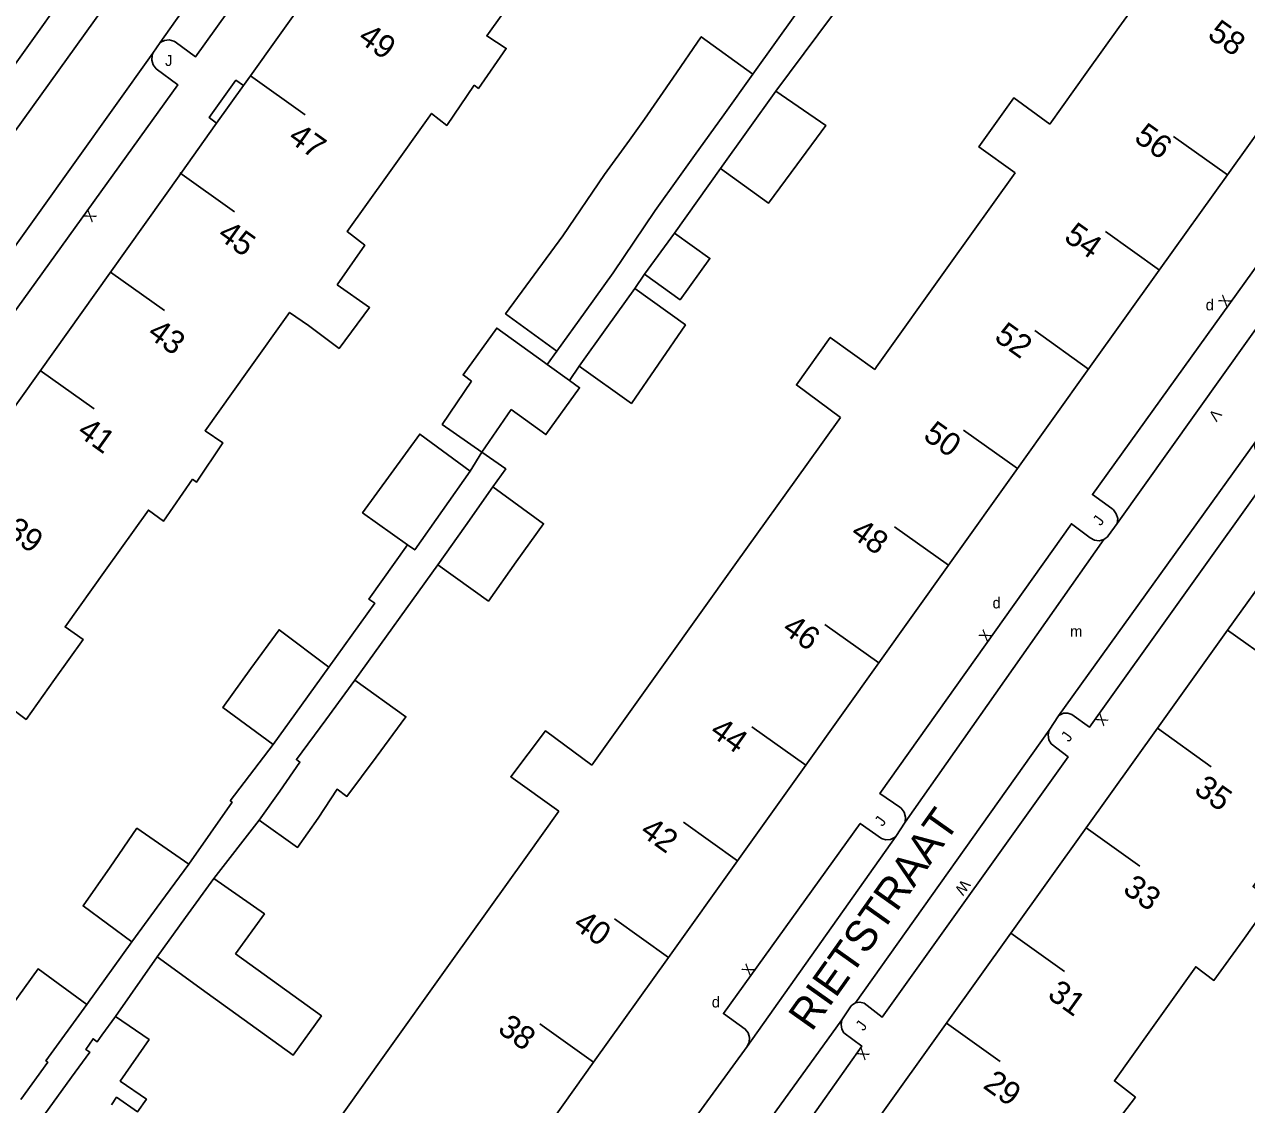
# Model space of a CAD drawing. Extents: x 134999 to 136502, y 457398 to 459002.
# Drawn here: x 135503.6 to 135559.1, y 457437.9 to 457486.9 of the extents above; entities that cross this region are included whole.
import ezdxf

# ---------------------------------------------------------------- set-up
doc = ezdxf.new("R2010")
doc.units = 0
for name, color, linetype in [('RI_DGTB_15', 7, 'Continuous'), ('RI_DGTB_29', 7, 'Continuous'), ('RI_DGTB_30', 7, 'Continuous'), ('RI_DGTB_31', 7, 'Continuous'), ('RI_DGTB_36', 7, 'Continuous'), ('RI_DGTB_37', 7, 'Continuous'), ('RI_DGTB_4', 7, 'Continuous'), ('RI_DGTB_43', 7, 'Continuous'), ('RI_DGTB_5', 7, 'Continuous'), ('RI_DGTB_53', 7, 'Continuous'), ('RI_DGTB_54', 7, 'Continuous'), ('RI_DGTB_6', 7, 'Continuous')]:
    doc.layers.add(name, color=color, linetype=linetype)

msp = doc.modelspace()

# ---------------------------------------------------------------- linework, layer by layer
at = {"layer": 'RI_DGTB_15'}
for p, q in [((135513.871, 457484.606), (135516.353, 457482.837)), ((135558.196, 457480.112), (135555.756, 457481.857)), ((135510.663, 457480.201), (135513.152, 457478.428)), ((135555.111, 457475.794), (135552.671, 457477.539)), ((135507.523, 457475.702), (135509.967, 457473.961)), ((135551.902, 457471.303), (135549.462, 457473.048)), ((135504.338, 457471.235), (135506.782, 457469.494)), ((135548.672, 457466.786), (135546.232, 457468.531)), ((135545.54, 457462.402), (135543.1, 457464.147)), ((135542.378, 457457.978), (135539.938, 457459.723)), ((135558.204, 457459.461), (135560.644, 457457.716)), ((135539.066, 457453.339), (135536.626, 457455.084)), ((135555.022, 457455.013), (135557.462, 457453.268)), ((135535.965, 457449.003), (135533.525, 457450.748)), ((135551.792, 457450.499), (135554.232, 457448.754)), ((135532.834, 457444.622), (135530.394, 457446.367)), ((135548.374, 457445.722), (135550.814, 457443.977)), ((135529.439, 457439.866), (135526.999, 457441.611)), ((135545.453, 457441.638), (135547.893, 457439.893))]:
    msp.add_line(p, q, dxfattribs=at)
at = {"layer": 'RI_DGTB_4'}
for p, q in [((135513.871, 457484.606), (135517.081, 457489.108)), ((135558.196, 457480.112), (135561.66, 457484.96)), ((135513.871, 457484.606), (135513.552, 457484.159)), ((135512.332, 457482.447), (135513.552, 457484.159)), ((135510.708, 457480.169), (135512.332, 457482.447)), ((135507.488, 457475.653), (135510.708, 457480.169)), ((135558.196, 457480.112), (135555.11, 457475.795)), ((135504.31, 457471.196), (135507.488, 457475.653)), ((135555.11, 457475.795), (135551.918, 457471.328)), ((135501.103, 457466.696), (135504.31, 457471.196)), ((135551.918, 457471.328), (135548.672, 457466.786)), ((135548.672, 457466.786), (135545.54, 457462.402)), ((135561.424, 457463.961), (135558.204, 457459.461)), ((135545.54, 457462.402), (135542.378, 457457.978)), ((135558.204, 457459.461), (135555.022, 457455.013)), ((135542.378, 457457.978), (135539.064, 457453.34)), ((135555.022, 457455.013), (135551.792, 457450.499)), ((135539.064, 457453.34), (135535.965, 457449.003)), ((135551.792, 457450.499), (135548.374, 457445.722)), ((135535.965, 457449.003), (135532.834, 457444.622)), ((135548.374, 457445.722), (135545.483, 457441.681)), ((135532.834, 457444.622), (135529.437, 457439.868)), ((135545.483, 457441.681), (135542.188, 457437.075)), ((135529.437, 457439.868), (135526.186, 457435.319))]:
    msp.add_line(p, q, dxfattribs=at)
at = {"layer": 'RI_DGTB_5'}
for p, q in [((135553.28, 457486.793), (135555.007, 457489.21)), ((135551.826, 457484.76), (135553.28, 457486.793)), ((135550.149, 457482.415), (135551.826, 457484.76)), ((135545.562, 457475.998), (135548.571, 457480.206)), ((135542.276, 457471.401), (135545.562, 457475.998)), ((135542.197, 457471.29), (135542.276, 457471.401)), ((135539.115, 457466.979), (135540.639, 457469.11)), ((135535.932, 457462.526), (135539.115, 457466.979)), ((135532.617, 457457.889), (135535.932, 457462.526)), ((135529.436, 457453.44), (135532.617, 457457.889)), ((135529.364, 457453.34), (135529.436, 457453.44)), ((135526.365, 457449.147), (135527.868, 457451.249)), ((135523.015, 457444.461), (135526.365, 457449.147)), ((135519.734, 457439.872), (135523.015, 457444.461)), ((135516.628, 457435.527), (135519.734, 457439.872)), ((135552.594, 457436.415), (135554.027, 457438.286))]:
    msp.add_line(p, q, dxfattribs=at)
for points in [[(135526.629, 457489.259), (135524.594, 457486.409), (135525.48, 457485.848), (135524.219, 457484.027), (135524.025, 457484.179)], [(135520.093, 457480.103), (135522.087, 457482.896), (135522.781, 457482.351), (135524.025, 457484.179)], [(135550.149, 457482.415), (135548.511, 457483.611), (135546.921, 457481.381), (135548.571, 457480.206)], [(135520.093, 457480.103), (135518.263, 457477.539), (135519.057, 457476.921), (135517.804, 457475.13)], [(135517.804, 457475.13), (135519.279, 457474.088), (135517.89, 457472.24), (135516.505, 457473.273)], [(135513.724, 457471.182), (135515.646, 457473.874), (135516.505, 457473.273)], [(135542.197, 457471.29), (135540.182, 457472.738), (135538.645, 457470.584), (135540.639, 457469.11)], [(135513.724, 457471.182), (135511.815, 457468.507), (135512.624, 457467.952), (135511.426, 457466.177), (135511.247, 457466.315)], [(135507.296, 457462.175), (135509.244, 457464.904), (135509.931, 457464.411), (135511.247, 457466.315)], [(135507.296, 457462.175), (135505.462, 457459.607), (135506.281, 457459.044), (135504.985, 457457.229)], [(135501.011, 457453.375), (135502.898, 457456.015), (135503.689, 457455.414), (135504.985, 457457.229)], [(135527.868, 457451.249), (135525.683, 457452.814), (135527.252, 457454.893), (135529.364, 457453.34)], [(135561.294, 457450.532), (135559.367, 457447.834), (135560.203, 457447.21), (135558.896, 457445.392)], [(135554.653, 457441.236), (135556.766, 457444.193), (135557.589, 457443.574), (135558.896, 457445.392)], [(135554.027, 457438.286), (135553.07, 457439.02), (135554.653, 457441.236)]]:
    msp.add_lwpolyline(points, dxfattribs=at)
at = {"layer": 'RI_DGTB_53'}
for p, q in [((135517.563, 457497.101), (135509.776, 457486.117)), ((135500, 457477.662), (135510.887, 457492.825)), ((135509.439, 457485.634), (135500, 457472.409)), ((135562.247, 457477), (135553.203, 457464.297)), ((135559.48, 457467.998), (135550.538, 457455.574)), ((135552.587, 457463.573), (135543.575, 457450.749)), ((135541.331, 457442.565), (135550.114, 457454.92)), ((135543.156, 457450.102), (135536.405, 457440.579)), ((135537.288, 457437.052), (135540.711, 457441.792))]:
    msp.add_line(p, q, dxfattribs=at)
at = {"layer": 'RI_DGTB_54'}
for p, q in [((135541.104, 457488.454), (135537.703, 457483.901)), ((135536.671, 457484.682), (135538.65, 457487.441)), ((135509.776, 457486.117), (135509.439, 457485.634)), ((135535.2, 457480.403), (135533.116, 457477.472)), ((135531.306, 457474.955), (135531.754, 457475.606)), ((135523.845, 457466.679), (135524.377, 457467.527)), ((135522.369, 457462.423), (135518.611, 457457.191)), ((135550.538, 457455.574), (135550.114, 457454.92)), ((135514.91, 457454.273), (135512.947, 457451.728)), ((135514.264, 457450.838), (135512.206, 457448.191)), ((135543.575, 457450.749), (135543.156, 457450.102)), ((135508.49, 457445.331), (135506.448, 457442.484)), ((135536.405, 457440.579), (135527.712, 457428.631))]:
    msp.add_line(p, q, dxfattribs=at)
for points in [[(135517.563, 457497.101), (135517.532, 457496.969), (135517.545, 457496.744), (135517.635, 457496.538), (135517.791, 457496.376), (135518.719, 457495.691), (135511.383, 457485.463), (135510.455, 457486.136), (135510.399, 457486.168), (135510.19, 457486.229), (135509.973, 457486.211), (135509.776, 457486.117)], [(135500, 457480.686), (135509.207, 457493.544), (135510.214, 457492.793), (135510.266, 457492.764), (135510.476, 457492.707), (135510.692, 457492.728), (135510.887, 457492.825)], [(135509.439, 457485.634), (135509.408, 457485.538), (135509.395, 457485.312), (135509.461, 457485.096), (135509.598, 457484.916), (135510.577, 457484.2), (135500.627, 457470.397), (135500, 457470.85)], [(135513.552, 457484.159), (135513.213, 457484.399), (135511.999, 457482.706), (135512.332, 457482.447)], [(135562.247, 457477), (135562.125, 457476.9), (135561.941, 457476.841), (135561.749, 457476.86), (135561.581, 457476.955), (135560.7, 457477.598), (135552.075, 457465.612), (135552.949, 457464.982), (135553.024, 457464.921), (135553.157, 457464.739), (135553.22, 457464.522), (135553.203, 457464.297)], [(135527.339, 457471.516), (135527.769, 457472.112)], [(135528.787, 457471.435), (135528.355, 457470.785)], [(135559.48, 457467.998), (135559.449, 457467.776), (135559.498, 457467.557), (135559.62, 457467.369), (135559.632, 457467.357), (135560.357, 457466.824), (135551.941, 457455.054), (135551.135, 457455.632), (135550.953, 457455.703), (135550.757, 457455.695), (135550.581, 457455.611), (135550.538, 457455.574)], [(135524.377, 457467.527), (135525.456, 457466.774), (135524.877, 457465.959)], [(135543.575, 457450.749), (135543.59, 457450.98), (135543.527, 457451.202), (135543.392, 457451.389), (135543.34, 457451.435), (135542.433, 457452.052), (135551.123, 457464.285), (135551.972, 457463.643), (135552.163, 457463.543), (135552.378, 457463.518), (135552.587, 457463.573)], [(135553.203, 457464.297), (135552.791, 457463.732), (135552.762, 457463.699), (135552.587, 457463.573)], [(135521.001, 457463.335), (135519.246, 457460.865), (135519.512, 457460.681), (135517.426, 457457.776)], [(135550.114, 457454.92), (135550.065, 457454.708), (135550.096, 457454.493), (135550.195, 457454.311), (135550.97, 457453.715), (135542.535, 457441.913), (135541.721, 457442.547), (135541.528, 457442.595), (135541.331, 457442.565)], [(135511.074, 457448.85), (135513.036, 457451.666), (135512.947, 457451.728)], [(135543.156, 457450.102), (135543.1, 457450.056), (135542.911, 457449.966), (135542.701, 457449.953), (135542.502, 457450.019), (135541.538, 457450.699), (135535.333, 457442.072), (135536.319, 457441.371), (135536.452, 457441.2), (135536.515, 457440.992), (135536.498, 457440.775), (135536.405, 457440.579)], [(135509.64, 457444.653), (135507.756, 457441.945)], [(135541.331, 457442.565), (135541.162, 457442.46), (135541.124, 457442.42), (135540.711, 457441.792)], [(135540.711, 457441.792), (135540.669, 457441.579), (135540.707, 457441.364), (135540.8, 457441.201), (135541.607, 457440.599), (135538.508, 457436.206), (135537.288, 457437.052)]]:
    msp.add_lwpolyline(points, dxfattribs=at)
at = {"layer": 'RI_DGTB_6'}
for p, q in [((135531.063, 457481.683), (135531.751, 457482.633)), ((135529.937, 457480.125), (135531.063, 457481.683)), ((135534.022, 457480.99), (135533.337, 457480.037)), ((135528.042, 457477.351), (135529.937, 457480.125)), ((135533.337, 457480.037), (135532.229, 457478.493)), ((135532.229, 457478.493), (135530.331, 457475.664)), ((135531.754, 457475.606), (135533.116, 457477.472))]:
    msp.add_line(p, q, dxfattribs=at)
for points in [[(135536.671, 457484.682), (135534.329, 457486.371), (135533.034, 457484.494)], [(135533.034, 457484.494), (135531.751, 457482.633)], [(135536.671, 457484.682), (135535.347, 457482.837)], [(135536.452, 457482.152), (135537.703, 457483.901)], [(135537.703, 457483.901), (135539.972, 457482.351), (135538.661, 457480.571)], [(135535.347, 457482.837), (135534.022, 457480.99)], [(135535.2, 457480.403), (135536.452, 457482.152)], [(135538.661, 457480.571), (135537.372, 457478.82), (135535.2, 457480.403)], [(135528.042, 457477.351), (135526.747, 457475.582)], [(135533.116, 457477.472), (135534.719, 457476.32), (135533.369, 457474.445), (135531.754, 457475.606)], [(135526.747, 457475.582), (135525.451, 457473.812), (135527.769, 457472.112)], [(135530.331, 457475.664), (135529.053, 457473.892)], [(135530.046, 457473.195), (135531.306, 457474.955)], [(135531.306, 457474.955), (135533.608, 457473.307), (135532.382, 457471.524)], [(135529.053, 457473.892), (135527.769, 457472.112)], [(135528.787, 457471.435), (135530.046, 457473.195)], [(135527.214, 457471.606), (135525.047, 457473.164), (135523.516, 457471.036), (135523.9, 457470.76)], [(135527.339, 457471.516), (135527.214, 457471.606)], [(135532.382, 457471.524), (135531.158, 457469.744), (135528.787, 457471.435)], [(135528.355, 457470.785), (135527.339, 457471.516)], [(135523.9, 457470.76), (135522.571, 457468.791), (135524.377, 457467.527)], [(135525.706, 457469.464), (135527.279, 457468.33), (135528.809, 457470.458), (135528.355, 457470.785)], [(135524.377, 457467.527), (135525.706, 457469.464)], [(135523.845, 457466.679), (135521.55, 457468.353), (135520.255, 457466.568)], [(135520.255, 457466.568), (135518.96, 457464.783), (135521.001, 457463.335)], [(135523.845, 457466.679), (135522.58, 457464.883)], [(135523.623, 457464.191), (135524.877, 457465.959)], [(135524.877, 457465.959), (135527.173, 457464.29), (135525.933, 457462.553)], [(135522.58, 457464.883), (135521.328, 457463.104), (135521.001, 457463.335)], [(135522.369, 457462.423), (135523.623, 457464.191)], [(135525.933, 457462.553), (135524.669, 457460.783), (135522.369, 457462.423)], [(135517.426, 457457.776), (135515.173, 457459.48), (135513.896, 457457.716)], [(135513.896, 457457.716), (135512.62, 457455.953), (135514.91, 457454.273)], [(135517.426, 457457.776), (135516.19, 457456.056)], [(135518.611, 457457.191), (135517.286, 457455.392)], [(135519.575, 457453.708), (135520.929, 457455.532), (135518.611, 457457.191)], [(135516.19, 457456.056), (135514.91, 457454.273)], [(135517.286, 457455.392), (135515.961, 457453.592), (135516.114, 457453.48), (135515.199, 457452.164)], [(135516.945, 457450.933), (135517.805, 457452.245), (135518.248, 457451.92), (135519.575, 457453.708)], [(135514.264, 457450.838), (135515.199, 457452.164)], [(135511.074, 457448.85), (135508.724, 457450.48), (135507.503, 457448.718)], [(135516.945, 457450.933), (135516.01, 457449.607), (135514.264, 457450.838)], [(135511.074, 457448.85), (135509.804, 457447.12)], [(135507.503, 457448.718), (135506.281, 457446.955), (135508.49, 457445.331)], [(135512.206, 457448.191), (135510.923, 457446.422)], [(135512.206, 457448.191), (135514.503, 457446.59), (135513.194, 457444.774)], [(135509.804, 457447.12), (135508.49, 457445.331)], [(135510.923, 457446.422), (135509.64, 457444.653)], [(135511.91, 457442.993), (135509.64, 457444.653)], [(135513.194, 457444.774), (135517.091, 457441.964), (135515.807, 457440.183), (135511.91, 457442.993)], [(135501.121, 457439.797), (135504.237, 457444.1), (135506.448, 457442.484)], [(135506.448, 457442.484), (135504.594, 457439.924), (135504.675, 457439.864), (135503.457, 457438.172)], [(135507.134, 457441.088), (135507.756, 457441.945)], [(135507.756, 457441.945), (135509.273, 457440.896), (135507.966, 457439.008), (135509.148, 457438.19), (135508.752, 457437.617), (135507.797, 457438.278), (135507.563, 457437.94)], [(135505.756, 457439.191), (135506.58, 457440.325), (135506.399, 457440.45), (135506.732, 457440.929), (135506.923, 457440.797), (135507.134, 457441.088)], [(135504.493, 457437.452), (135505.756, 457439.191)]]:
    msp.add_lwpolyline(points, dxfattribs=at)

# ---------------------------------------------------------------- texts
at = {"layer": 'RI_DGTB_29'}
for p in [(135557.214, 457473.964), (135547.542, 457460.448), (135534.804, 457442.349)]:
    msp.add_text('d', height=0.5, dxfattribs=at).set_placement(p)
at = {"layer": 'RI_DGTB_30'}
for s, rotation, p in [('X', 234.2113, (135506.52, 457478.571)), ('X', 54.5199, (135558.158, 457474.064)), ('V', 232.4765, (135557.582, 457469.537)), ('X', 54.5199, (135547.289, 457458.889)), ('X', 232.4765, (135552.434, 457455.728)), ('W', 234.4463, (135546.171, 457448.192)), ('X', 54.5199, (135536.529, 457443.734)), ('X', 232.4765, (135541.601, 457440.573))]:
    msp.add_text(s, height=0.499, rotation=rotation, dxfattribs=at).set_placement(p)
at = {"layer": 'RI_DGTB_31'}
msp.add_text('J', height=0.5, dxfattribs=at).set_placement((135509.998, 457485.048))
for p in [(135552.45, 457464.159), (135551.009, 457454.351), (135542.555, 457450.523), (135541.691, 457441.248)]:
    msp.add_text('J', height=0.499, rotation=54.4415, dxfattribs=at).set_placement(p)
at = {"layer": 'RI_DGTB_36'}
for s, rotation, p in [('58', 324.4462, (135557.244, 457486.361)), ('49', 324.5131, (135518.694, 457486.199)), ('47', 324.5131, (135515.524, 457481.676)), ('56', 324.4462, (135553.912, 457481.68)), ('45', 324.5131, (135512.324, 457477.266)), ('54', 324.4462, (135550.728, 457477.171)), ('43', 324.5131, (135509.139, 457472.799)), ('52', 324.4462, (135547.568, 457472.645)), ('41', 324.5131, (135505.954, 457468.331)), ('50', 324.4462, (135544.344, 457468.165)), ('39', 324.5131, (135502.693, 457463.811)), ('48', 324.4462, (135541.041, 457463.741)), ('46', 324.4462, (135537.942, 457459.394)), ('44', 324.4462, (135534.657, 457454.735)), ('35', 324.4141, (135556.63, 457452.108)), ('42', 324.4462, (135531.495, 457450.21)), ('33', 324.4141, (135553.401, 457447.593)), ('40', 324.4462, (135528.459, 457445.994)), ('31', 324.4141, (135549.983, 457442.816)), ('38', 324.4462, (135525.038, 457441.258)), ('29', 324.4141, (135547.062, 457438.732))]:
    msp.add_text(s, height=1.054, rotation=rotation, dxfattribs=at).set_placement(p)
at = {"layer": 'RI_DGTB_37'}
msp.add_text('RIETSTRAAT', height=1.4, rotation=54.668, dxfattribs=at).set_placement((135539.336, 457441.213))
at = {"layer": 'RI_DGTB_43'}
msp.add_text('m', height=0.5, dxfattribs=at).set_placement((135551.063, 457459.159))

doc.saveas('drawing.dxf')
